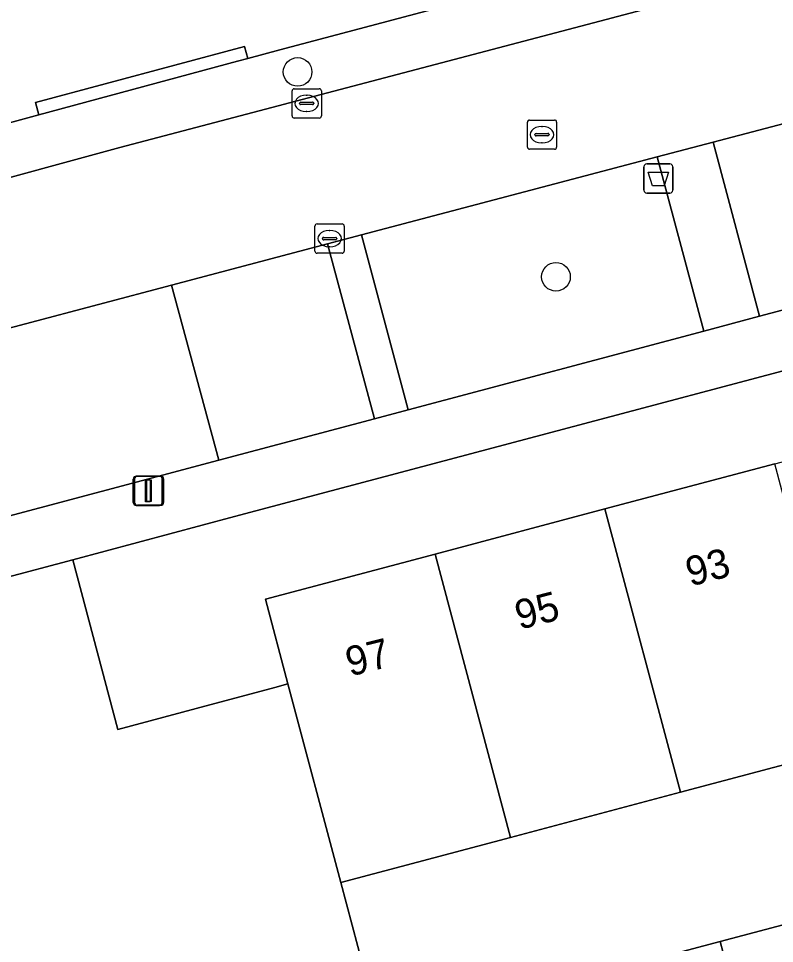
# Model space of a CAD drawing. Extents: x 162542 to 163147, y 380779 to 381521.
# Drawn here: x 162936.38 to 162962.19, y 381152.86 to 381184.48 of the extents above; entities that cross this region are included whole.
import ezdxf

# ---------------------------------------------------------------- set-up
doc = ezdxf.new("R2010")
doc.units = 0
for name, color, linetype in [('IMGEO_Afvalbak', 7, 'Continuous'), ('IMGEO_Boom', 7, 'Continuous'), ('IMGEO_Erf', 7, 'Continuous'), ('IMGEO_Groenvoorziening', 7, 'Continuous'), ('IMGEO_Kolk', 7, 'Continuous'), ('IMGEO_Lichtmast', 7, 'Continuous'), ('IMGEO_Muur', 7, 'Continuous'), ('IMGEO_Pand', 7, 'Continuous'), ('IMGEO_Pand_nummerreeks', 7, 'Continuous'), ('IMGEO_Parkeervlak_open', 7, 'Continuous'), ('IMGEO_Rijbaan_lokaal_open', 7, 'Continuous'), ('IMGEO_Rioolput', 7, 'Continuous'), ('IMGEO_Voetpad_open', 7, 'Continuous')]:
    doc.layers.add(name, color=color, linetype=linetype)

msp = doc.modelspace()

# ---------------------------------------------------------------- linework, layer by layer
at = {"layer": 'IMGEO_Afvalbak'}
for p, q in [((162957.733, 381178.613), (162957.733, 381179.413)), ((162957.733, 381179.413), (162957.733, 381178.613)), ((162957.833, 381179.513), (162958.623, 381179.513)), ((162958.623, 381179.513), (162957.833, 381179.513)), ((162958.723, 381179.413), (162958.723, 381178.613)), ((162958.723, 381178.613), (162958.723, 381179.413)), ((162958.623, 381178.513), (162957.833, 381178.513)), ((162957.833, 381178.513), (162958.623, 381178.513))]:
    msp.add_line(p, q, dxfattribs=at)
msp.add_lwpolyline([(162957.876, 381179.227), (162958.58, 381179.227), (162958.431, 381178.757), (162958.025, 381178.757), (162957.876, 381179.227)], dxfattribs=at)
for centre, start, end in [((162957.833, 381179.413), 90, 180), ((162957.833, 381179.413), 90, 180), ((162958.623, 381179.413), 0, 90), ((162958.623, 381179.413), 360, 90), ((162957.833, 381178.613), 180, 270), ((162957.833, 381178.613), 180, 270), ((162958.623, 381178.613), 270, 0), ((162958.623, 381178.613), 270, 0)]:
    msp.add_arc(centre, 0.1, start, end, dxfattribs=at)
at = {"layer": 'IMGEO_Boom'}
for centre in [(162945.909, 381182.656), (162954.732, 381175.653)]:
    msp.add_circle(centre, 0.489, dxfattribs=at)
at = {"layer": 'IMGEO_Erf'}
for points in [[(163005.842, 381183.958), (162943.75, 381167.455), (162938.228, 381165.977), (162939.768, 381160.178), (162942.447, 381160.897), (162945.126, 381161.616), (162945.58, 381161.738), (162944.809, 381164.636), (162950.607, 381166.178), (162956.406, 381167.72), (162962.204, 381169.262), (162968.003, 381170.804), (162973.801, 381172.346), (162979.6, 381173.888), (162985.398, 381175.43), (162991.196, 381176.972), (162996.995, 381178.514), (163002.793, 381180.057)], [(163005.368, 381170.374), (162999.569, 381168.831), (162993.771, 381167.289), (162987.973, 381165.746), (162982.174, 381164.204), (162976.376, 381162.661), (162970.578, 381161.118), (162964.779, 381159.576), (162958.981, 381158.033), (162953.183, 381156.491), (162947.385, 381154.948), (162948.742, 381149.846)], [(162956.042, 381151.788), (162960.338, 381152.931), (162964.594, 381154.064), (162965.416, 381150.972)]]:
    msp.add_lwpolyline(points, dxfattribs=at)
at = {"layer": 'IMGEO_Groenvoorziening'}
for points in [[(162971.713, 381176.963), (162970.109, 381182.891), (162960.101, 381180.253), (162961.683, 381174.305)], [(162958.186, 381179.749), (162948.093, 381177.085), (162949.683, 381171.106), (162959.78, 381173.79)], [(162946.927, 381176.777), (162941.6, 381175.367), (162943.223, 381169.386), (162948.531, 381170.8)], [(162941.6, 381175.367), (162931.623, 381172.725), (162933.078, 381166.682), (162943.223, 381169.386)]]:
    msp.add_lwpolyline(points, close=True, dxfattribs=at)
at = {"layer": 'IMGEO_Kolk'}
for p, q in [((162945.718, 381181.154), (162945.718, 381182.006)), ((162945.793, 381182.08), (162946.645, 381182.08)), ((162946.206, 381181.86), (162946.231, 381181.86)), ((162946.719, 381182.006), (162946.719, 381181.154)), ((162945.977, 381181.574), (162945.977, 381181.586)), ((162946.415, 381181.537), (162946.017, 381181.537)), ((162946.02, 381181.623), (162946.418, 381181.623)), ((162946.461, 381181.586), (162946.461, 381181.574)), ((162946.229, 381181.3), (162946.204, 381181.3)), ((162946.645, 381181.08), (162945.793, 381181.08)), ((162946.576, 381177.459), (162947.428, 381177.459)), ((162946.501, 381176.533), (162946.501, 381177.385)), ((162946.989, 381177.239), (162947.014, 381177.239)), ((162947.502, 381177.385), (162947.502, 381176.533)), ((162946.76, 381176.953), (162946.76, 381176.965)), ((162947.198, 381176.916), (162946.8, 381176.916)), ((162946.803, 381177.002), (162947.201, 381177.002)), ((162947.244, 381176.965), (162947.244, 381176.953)), ((162947.428, 381176.459), (162946.576, 381176.459)), ((162947.012, 381176.679), (162946.987, 381176.679))]:
    msp.add_line(p, q, dxfattribs=at)
for points in [[(162945.718, 381181.154), (162945.718, 381182.006)], [(162945.793, 381182.08), (162946.645, 381182.08)], [(162946.719, 381182.006), (162946.719, 381181.154)], [(162946.645, 381181.08), (162945.793, 381181.08)], [(162946.576, 381177.459), (162947.428, 381177.459)], [(162946.501, 381176.533), (162946.501, 381177.385)], [(162947.502, 381177.385), (162947.502, 381176.533)], [(162947.428, 381176.459), (162946.576, 381176.459)]]:
    msp.add_lwpolyline(points, dxfattribs=at)
for centre, radius, start, end in [((162945.795, 381182.004), 0.0765, 91.552, 178.448), ((162945.795, 381182.004), 0.0765, 91.552, 178.448), ((162946.643, 381182.004), 0.0765, 1.552, 88.448), ((162946.643, 381182.004), 0.0765, 1.552, 88.448), ((162946.017, 381181.583), 0.0403, 85.8775, 175.7526), ((162946.014, 381181.573), 0.0366, 178.938, 274.7102), ((162946.418, 381181.58), 0.043, 264.8664, 352.4533), ((162946.422, 381181.585), 0.0386, 1.7309, 96.639), ((162945.795, 381181.156), 0.0765, 181.552, 268.448), ((162945.795, 381181.156), 0.0765, 181.552, 268.448), ((162946.643, 381181.156), 0.0765, 271.552, 358.448), ((162946.643, 381181.156), 0.0765, 271.552, 358.448), ((162946.578, 381177.383), 0.0765, 91.552, 178.448), ((162946.578, 381177.383), 0.0765, 91.552, 178.448), ((162947.426, 381177.383), 0.0765, 1.552, 88.448), ((162947.426, 381177.383), 0.0765, 1.552, 88.448), ((162946.8, 381176.962), 0.0403, 85.8775, 175.7526), ((162946.797, 381176.952), 0.0366, 178.938, 274.7102), ((162947.201, 381176.959), 0.043, 264.8664, 352.4533), ((162947.205, 381176.964), 0.0386, 1.7309, 96.639), ((162946.578, 381176.535), 0.0765, 181.552, 268.448), ((162946.578, 381176.535), 0.0765, 181.552, 268.448), ((162947.426, 381176.535), 0.0765, 271.552, 358.448), ((162947.426, 381176.535), 0.0765, 271.552, 358.448)]:
    msp.add_arc(centre, radius, start, end, dxfattribs=at)
for centre, major_axis, ratio, start_param, end_param in [((162946.205, 381181.58), (-0.387, 0.002), 0.722429, 4.712389, 7.853982), ((162946.23, 381181.58), (-0.39, 0.002), 0.717154, 1.570796, 4.712389), ((162946.988, 381176.959), (-0.387, 0.002), 0.722429, 4.712389, 7.853982), ((162947.013, 381176.959), (-0.39, 0.002), 0.717154, 1.570796, 4.712389)]:
    msp.add_ellipse(centre, major_axis=major_axis, ratio=ratio, start_param=start_param, end_param=end_param, dxfattribs=at)
at = {"layer": 'IMGEO_Lichtmast'}
for p, q in [((162940.298, 381167.94), (162940.298, 381168.74)), ((162940.298, 381168.74), (162940.298, 381167.94)), ((162940.341, 381167.942), (162940.341, 381168.742)), ((162940.341, 381168.742), (162940.341, 381167.942)), ((162940.398, 381168.84), (162941.188, 381168.84)), ((162941.188, 381168.84), (162940.398, 381168.84)), ((162940.441, 381168.842), (162941.231, 381168.842)), ((162941.231, 381168.842), (162940.441, 381168.842)), ((162941.288, 381168.74), (162941.288, 381167.94)), ((162941.288, 381167.94), (162941.288, 381168.74)), ((162941.331, 381168.742), (162941.331, 381167.942)), ((162941.331, 381167.942), (162941.331, 381168.742)), ((162941.188, 381167.84), (162940.398, 381167.84)), ((162940.398, 381167.84), (162941.188, 381167.84)), ((162941.231, 381167.842), (162940.441, 381167.842)), ((162940.441, 381167.842), (162941.231, 381167.842))]:
    msp.add_line(p, q, dxfattribs=at)
for points in [[(162940.718, 381168.715), (162940.868, 381168.715), (162940.868, 381167.965), (162940.718, 381167.965), (162940.718, 381168.715)], [(162940.761, 381168.717), (162940.911, 381168.717), (162940.911, 381167.967), (162940.761, 381167.967), (162940.761, 381168.717)]]:
    msp.add_lwpolyline(points, dxfattribs=at)
for centre, start, end in [((162940.398, 381168.74), 90, 180), ((162940.398, 381168.74), 90, 180), ((162940.441, 381168.742), 90, 180), ((162940.441, 381168.742), 90, 180), ((162941.188, 381168.74), 0, 90), ((162941.188, 381168.74), 360, 90), ((162941.231, 381168.742), 0, 90), ((162941.231, 381168.742), 360, 90), ((162940.398, 381167.94), 180, 270), ((162940.398, 381167.94), 180, 270), ((162940.441, 381167.942), 180, 270), ((162940.441, 381167.942), 180, 270), ((162941.188, 381167.94), 270, 0), ((162941.188, 381167.94), 270, 0), ((162941.231, 381167.942), 270, 0), ((162941.231, 381167.942), 270, 0)]:
    msp.add_arc(centre, 0.1, start, end, dxfattribs=at)
at = {"layer": 'IMGEO_Muur'}
msp.add_lwpolyline([(162943.75, 381167.455), (162938.228, 381165.977)], dxfattribs=at)
at = {"layer": 'IMGEO_Pand'}
for points in [[(162962.204, 381169.262), (162956.406, 381167.72), (162958.981, 381158.033), (162964.779, 381159.576)], [(162950.607, 381166.178), (162953.183, 381156.491), (162958.981, 381158.033), (162956.406, 381167.72)], [(162950.607, 381166.178), (162944.809, 381164.636), (162945.58, 381161.738), (162947.385, 381154.948), (162953.183, 381156.491)], [(162947.385, 381154.948), (162945.58, 381161.738), (162945.126, 381161.616), (162942.447, 381160.897), (162939.768, 381160.178), (162938.228, 381165.977), (162926.213, 381162.787), (162927.747, 381156.998), (162921.959, 381155.449), (162925.16, 381143.411), (162930.943, 381144.949), (162932.49, 381139.157), (162944.529, 381142.345), (162943.016, 381148.152), (162948.785, 381149.681), (162948.742, 381149.846)], [(162964.594, 381154.064), (162960.338, 381152.931), (162961.16, 381149.839), (162965.416, 381150.972)], [(162960.338, 381152.931), (162956.042, 381151.788), (162956.865, 381148.696), (162961.16, 381149.839)]]:
    msp.add_lwpolyline(points, close=True, dxfattribs=at)
at = {"layer": 'IMGEO_Parkeervlak_open'}
msp.add_lwpolyline([(162945.307, 381183.409), (162944.204, 381183.118), (162943.854, 381183.025), (162937.074, 381181.191), (162920.542, 381176.676), (162920.963, 381174.947), (162923.178, 381175.528), (162939.834, 381180.075), (163029.671, 381203.749), (163029.17, 381205.595), (163009.881, 381200.547), (163008.469, 381200.178), (162968.263, 381189.504)], close=True, dxfattribs=at)
at = {"layer": 'IMGEO_Rijbaan_lokaal_open'}
msp.add_lwpolyline([(163029.671, 381203.749), (162939.834, 381180.075), (162923.178, 381175.528), (162924.413, 381170.816), (162930.38, 381172.396), (162931.623, 381172.725), (162941.6, 381175.367), (162946.927, 381176.777), (162948.093, 381177.085), (162958.186, 381179.749), (162960.101, 381180.253), (162970.109, 381182.891), (162971.268, 381183.196), (162981.715, 381185.95), (162982.865, 381186.253), (162993.306, 381189.004), (162994.468, 381189.311), (163004.787, 381192.03)], dxfattribs=at)
at = {"layer": 'IMGEO_Rioolput'}
for p, q in [((162953.754, 381180.086), (162953.754, 381180.938)), ((162953.829, 381181.012), (162954.681, 381181.012)), ((162954.755, 381180.938), (162954.755, 381180.086)), ((162954.056, 381180.555), (162954.454, 381180.555)), ((162954.242, 381180.792), (162954.267, 381180.792)), ((162954.013, 381180.506), (162954.013, 381180.518)), ((162954.451, 381180.469), (162954.053, 381180.469)), ((162954.497, 381180.518), (162954.497, 381180.506)), ((162954.681, 381180.012), (162953.829, 381180.012)), ((162954.265, 381180.232), (162954.24, 381180.232))]:
    msp.add_line(p, q, dxfattribs=at)
for points in [[(162953.754, 381180.086), (162953.754, 381180.938)], [(162953.829, 381181.012), (162954.681, 381181.012)], [(162954.755, 381180.938), (162954.755, 381180.086)], [(162954.681, 381180.012), (162953.829, 381180.012)]]:
    msp.add_lwpolyline(points, dxfattribs=at)
for centre, radius, start, end in [((162953.831, 381180.936), 0.0765, 91.552, 178.448), ((162953.831, 381180.936), 0.0765, 91.552, 178.448), ((162954.679, 381180.936), 0.0765, 1.552, 88.448), ((162954.679, 381180.936), 0.0765, 1.552, 88.448), ((162954.053, 381180.515), 0.0403, 85.8775, 175.7526), ((162954.458, 381180.517), 0.0386, 1.7309, 96.639), ((162954.05, 381180.505), 0.0366, 178.938, 274.7102), ((162954.454, 381180.512), 0.043, 264.8664, 352.4533), ((162953.831, 381180.088), 0.0765, 181.552, 268.448), ((162953.831, 381180.088), 0.0765, 181.552, 268.448), ((162954.679, 381180.088), 0.0765, 271.552, 358.448), ((162954.679, 381180.088), 0.0765, 271.552, 358.448)]:
    msp.add_arc(centre, radius, start, end, dxfattribs=at)
for centre, major_axis, ratio, start_param, end_param in [((162954.241, 381180.512), (-0.387, 0.002), 0.722429, 4.712389, 7.853982), ((162954.266, 381180.512), (-0.39, 0.002), 0.717154, 1.570796, 4.712389)]:
    msp.add_ellipse(centre, major_axis=major_axis, ratio=ratio, start_param=start_param, end_param=end_param, dxfattribs=at)
at = {"layer": 'IMGEO_Voetpad_open'}
for points in [[(162850.91, 381158.201), (162882.303, 381166.521), (162903.648, 381172.331), (162920.542, 381176.676), (162937.074, 381181.191), (162936.958, 381181.61), (162944.091, 381183.522), (162944.204, 381183.118), (162945.307, 381183.409), (162968.263, 381189.504), (162966.757, 381191.138), (162965.477, 381192.532), (162963.89, 381194.094), (162959.774, 381198.46), (162951.248, 381207.533), (162947.383, 381211.626), (162906.029, 381255.574)], [(163006.379, 381186.176), (162996.039, 381183.424), (162994.892, 381183.118), (162984.447, 381180.339), (162983.289, 381180.032), (162972.863, 381177.268), (162971.713, 381176.963), (162961.683, 381174.305), (162959.78, 381173.79), (162949.683, 381171.106), (162948.531, 381170.8), (162943.223, 381169.386), (162933.078, 381166.682), (162931.869, 381166.36), (162921.592, 381163.621), (162919.888, 381163.169), (162920.409, 381161.252), (162926.213, 381162.787), (162938.228, 381165.977), (162943.75, 381167.455), (163005.842, 381183.958)]]:
    msp.add_lwpolyline(points, dxfattribs=at)
for points in [[(162937.074, 381181.191), (162943.854, 381183.025), (162944.204, 381183.118), (162944.091, 381183.522), (162936.958, 381181.61)], [(162959.78, 381173.79), (162961.683, 381174.305), (162960.101, 381180.253), (162958.186, 381179.749)], [(162948.531, 381170.8), (162949.683, 381171.106), (162948.093, 381177.085), (162946.927, 381176.777)]]:
    msp.add_lwpolyline(points, close=True, dxfattribs=at)

# ---------------------------------------------------------------- texts
at = {"layer": 'IMGEO_Pand_nummerreeks'}
for s, rotation, p in [('93', 14.6568, (162959.317, 381165.062)), ('95', 14.5143, (162953.484, 381163.583)), ('97', 14.1062, (162947.695, 381161.987))]:
    msp.add_text(s, height=1, rotation=rotation, dxfattribs=at).set_placement(p)

doc.saveas('drawing.dxf')
